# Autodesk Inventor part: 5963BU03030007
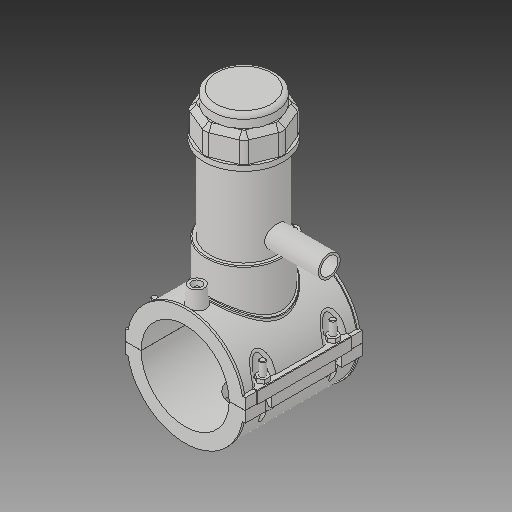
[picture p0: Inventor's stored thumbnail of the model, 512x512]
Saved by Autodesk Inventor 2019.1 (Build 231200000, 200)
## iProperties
Created: 2017-07
Part Number: 5963BU03030007
Material: Generic
Description: PLASSON TAPPING SADDLE 3''IPS x 1 3/4''CTS
Document SubType Name: Modeling
Designer: KIM
Mass: 1712.7 g
Surface Area: 2671.49 cm^2
Volume: 1712.7 cm^3
Density: 1 g/cm^3
Appearance: Default
Author: KIM
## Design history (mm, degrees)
derived "5963B.ipt"
feature "Solid1::5963B.ipt"
feature "Solid2::5963B.ipt"
feature "Solid4::5963B.ipt"
feature "Solid5::5963B.ipt"
tag "TaggingFeature1"
body "Solid1"
body "Solid2"
other parameters: "d0" = 88.7, "d2" = 120.904, "d3" = 22.175, "d4" = 118.11, "d5" = 0, "d6" = 0.1, "d8" = 0, "d19" = 6, "d20" = 6, "d21" = 70.866, "d23" = 0, "d24" = 35.433, "d26" = 0, "d29" = 3, "d30" = 29.56667, "d31" = 6, "d32" = 0, "d33" = 0, "d34" = 0.6, "d40" = 59.9612, "d41" = 79.83, "d43" = 0, "d45" = 0, "d47" = 128.521, "d70" = 15, "d72" = 0, "d73" = 6, "d75" = 5, "d76" = 0, "d77" = 4.435, "d78" = 74.35, "d79" = 15, "d80" = 47.244, "d82" = 5 deg, "d84" = 4, "d85" = 14, "d86" = 0, "d87" = 3, "d88" = 0, "d89" = 1, "d90" = 1, "d91" = 94.488, "d92" = 0, "d93" = 0.5, "d94" = 46.68421, "d96" = 117.6162, "d97" = 2.3622, "d98" = 0, "d102" = 0.887, "d120" = 140 deg, "d121" = 24.228, "d122" = 20 deg, "d123" = 230.62, "d124" = 69.186, "d126" = 0, "d143" = 91.361, "d145" = 20.46923, "d149" = 1.3305, "d150" = 22.51615, "d153" = 118.11, "d154" = 0, "d156" = 57.655, "d157" = 160 deg, "d159" = 5.322, "d161" = 1.3305, "d162" = 70.866, "d163" = 0, "d164" = 44.35, "d167" = 8.87, "d168" = 56.24878, "d170" = 3.2805, "d172" = 0, "d173" = 1, "d175" = 44.35, "d176" = 20 deg, "d177" = 6.209, "d178" = 26.61, "d180" = 0, "d183" = 10.644, "d184" = 4.9672, "d185" = 38.38575, "d186" = 38.38575, "d187" = 57.655, "d188" = 7.983, "d189" = 6.209, "d190" = 0, "d191" = 86.4825, "d193" = 6.1236, "d194" = 4.13385, "d195" = 90 deg, "d197" = 0, "d199" = 0, "d200" = 13.305, "d202" = 0, "d203" = 177.038, "d204" = 75.8385, "d205" = 55.881, "d206" = 67.8555, "d207" = 132.7785, "d208" = 138.08964, "d209" = 164.64534, "d210" = 68.6538, "d211" = 79.83, "d212" = 63.864, "d213" = 48.5766, "d216" = 0, "d217" = 8.87, "d218" = 4.435, "d219" = 0.887, "d222" = 88.7, "d224" = 0, "d230" = 5.322, "d233" = 6, "d236" = 60.452, "d237" = 35.433, "d238" = 6.02433, "d240" = 35.433, "d241" = 35.433, "d242" = 35.433, "d243" = 6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
